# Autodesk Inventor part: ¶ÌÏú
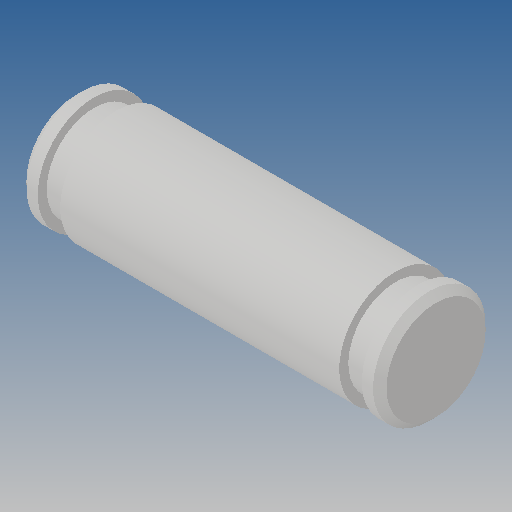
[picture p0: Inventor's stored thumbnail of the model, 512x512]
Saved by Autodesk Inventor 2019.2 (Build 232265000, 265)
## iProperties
Created: 2013-07
Part Number: ¶ÌÏú
Material: Ogólny
Document SubType Name: Modeling
Designer: CADENGINEERING4
Density: 1 g/cm^3
Appearance: Domyślna
Author: CADENGINEERING4
Revision Number: ÈÎºÎ
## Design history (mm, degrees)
feature "Ðý×ª1"
node "Bryła1"
